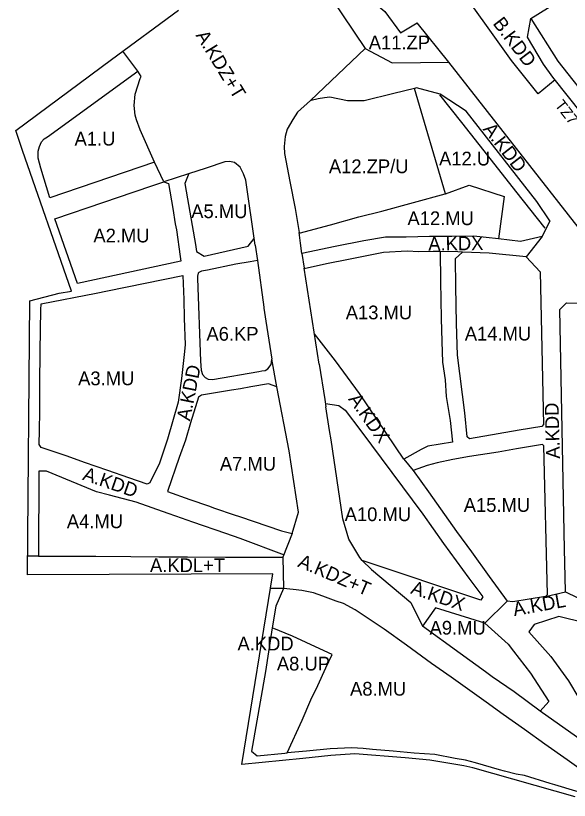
# Model space of a CAD drawing. Extents: x -292612 to -290407, y 29458 to 30862.
# Drawn here: x -292612 to -292209, y 29782 to 30353 of the extents above; entities that cross this region are included whole.
import ezdxf

# ---------------------------------------------------------------- set-up
doc = ezdxf.new("R2010")
doc.units = 0
for name, color, linetype in [('linie_rozgraniczajace', 7, 'Continuous'), ('linie_zabudowy_obowiazujace', 7, 'Continuous'), ('oznaczenia_przeznaczen', 7, 'Continuous')]:
    doc.layers.add(name, color=color, linetype=linetype)

msp = doc.modelspace()

# ---------------------------------------------------------------- linework, layer by layer
at = {"layer": 'linie_rozgraniczajace'}
for p, q in [((-292390.83, 30378.76), (-292357.67, 30329.25)), ((-292542.22, 30321.16), (-292493.29, 30357.16)), ((-292523.04, 30312.71), (-292533.81, 30327.34)), ((-292357.67, 30329.25), (-292397.33, 30291.25)), ((-292611.86, 30269.51), (-292542.22, 30321.16)), ((-292178.26, 30167.91), (-292296.67, 30319.14)), ((-292299.21, 30223.36), (-292321.61, 30300.14)), ((-292606.96, 30254.87), (-292611.86, 30269.51)), ((-292571.33, 30152.6), (-292606.96, 30254.87)), ((-292437.58, 30186.09), (-292435.97, 30174.79)), ((-292403.64, 30180.1), (-292401.98, 30169.39)), ((-292580.18, 30151.09), (-292571.33, 30152.6)), ((-292601.58, 30145.42), (-292580.18, 30151.09)), ((-292603.2, 29946.19), (-292601.58, 30145.42)), ((-292421.92, 30082.83), (-292425.54, 30102.98)), ((-292329.32, 30030.37), (-292322.65, 30022.04)), ((-292410.78, 29976.21), (-292417.39, 29959.06)), ((-292595.34, 29959.68), (-292603.09, 29959.74)), ((-292459.15, 29959.06), (-292417.39, 29959.06)), ((-292424.73, 29946.92), (-292603.2, 29946.19)), ((-292447.34, 29808.03), (-292424.73, 29946.92)), ((-292226.31, 29930.42), (-292211.9, 29933.7)), ((-292270.59, 29910.82), (-292254.33, 29927.03)), ((-292171.12, 29805.01), (-292230.27, 29846.8)), ((-292365.11, 29815.79), (-292382.58, 29814.73)), ((-292328.51, 29812.84), (-292365.11, 29815.79)), ((-292403, 29812.31), (-292447.34, 29808.03)), ((-292382.58, 29814.73), (-292403, 29812.31)), ((-292310.52, 29811.17), (-292328.51, 29812.84)), ((-292285.82, 29807.07), (-292310.52, 29811.17)), ((-292279.28, 29805.58), (-292285.82, 29807.07)), ((-292204.65, 29784.63), (-292279.28, 29805.58))]:
    msp.add_line(p, q, dxfattribs=at)
for points in [[(-292219.42, 30306.28), (-292231.76, 30296.25), (-292251.12, 30320.42), (-292294.16, 30381.19), (-292326.04, 30429.67), (-292332, 30438.9)], [(-292373.59, 30428.73), (-292377.61, 30422.97), (-292389.1, 30408.68), (-292386.8, 30405.09), (-292384.81, 30401.99), (-292384.04, 30400.78), (-292372.52, 30382.87), (-292369.66, 30378.43), (-292362.11, 30372.05), (-292343.34, 30356.18), (-292343.15, 30356.02), (-292331.87, 30340.69), (-292319.82, 30347.9)], [(-292104.75, 30221.08), (-292119.95, 30209.73), (-292121.9, 30208.54), (-292128.67, 30207.44), (-292137.35, 30208.56), (-292139.58, 30209.07), (-292145.2, 30212.99), (-292221.03, 30308.3), (-292227.7, 30317.87), (-292239.51, 30337.34), (-292236.95, 30350.95), (-292118.95, 30424.55), (-292105.07, 30421.42), (-292048.46, 30333.06)], [(-292296.67, 30319.14), (-292319.84, 30347.78)], [(-292357.67, 30329.25), (-292337.84, 30318.78), (-292296.67, 30319.14)], [(-292510.88, 30246.53), (-292586.98, 30220.6), (-292593.61, 30242.05), (-292595.6, 30249.37), (-292595.46, 30254.49), (-292594.55, 30257.84), (-292593.07, 30261.14), (-292591.05, 30263.39), (-292588.72, 30265.01), (-292523.04, 30312.71)], [(-292510.88, 30246.53), (-292521.31, 30269.91), (-292523.96, 30277.35), (-292524.82, 30280.64), (-292525.6, 30287.72), (-292525.04, 30295.91), (-292521.2, 30307.37), (-292520.59, 30308.76), (-292523.04, 30312.71)], [(-292321.61, 30300.14), (-292336.68, 30296.44), (-292358.39, 30291.14), (-292370.54, 30291.21), (-292383.33, 30293.83), (-292387.1, 30293.18), (-292391.72, 30292.58), (-292396.92, 30291.46), (-292397.33, 30291.26)], [(-292223.31, 30203.67), (-292232.56, 30217.79), (-292284.14, 30283.67), (-292303.11, 30295.89), (-292320.16, 30300.49), (-292321.61, 30300.14)], [(-292397.33, 30291.26), (-292406.71, 30282.73), (-292410.29, 30277.51), (-292414.35, 30270.36), (-292415.9, 30265.22), (-292416.41, 30257.98), (-292416.28, 30252.75), (-292412.45, 30232.41), (-292408.61, 30212.68), (-292405.65, 30195.25)], [(-292503.99, 30232.22), (-292510.88, 30246.53)], [(-292437.58, 30186.09), (-292444.36, 30233.36), (-292446, 30238.08), (-292448.6, 30242.87), (-292452.61, 30246.1), (-292456.33, 30247.03), (-292459.78, 30246.62), (-292473.34, 30242.16), (-292486.19, 30237.93)], [(-292485.8, 30238.24), (-292488.68, 30230.98), (-292486.79, 30219.73), (-292481.07, 30186.55), (-292480.24, 30181.44), (-292474.74, 30178.07), (-292442.66, 30185.3), (-292438.22, 30190.92)], [(-292486.19, 30237.93), (-292503.99, 30232.22)], [(-292503.99, 30232.22), (-292500.62, 30230.94), (-292497.52, 30212.79), (-292495.74, 30201.65), (-292494.89, 30197.18), (-292492.14, 30177.89), (-292491.64, 30174.43), (-292566.86, 30158.22), (-292583.32, 30205.12), (-292547.61, 30217.29), (-292526.5, 30224.54), (-292511.45, 30229.74), (-292503.99, 30232.22)], [(-292299.21, 30223.36), (-292281.9, 30229.74), (-292256.51, 30221.54), (-292260.56, 30190.72)], [(-292405.58, 30194.82), (-292382.74, 30200.76), (-292362.12, 30206.63), (-292345.4, 30210.81), (-292299.25, 30223.35), (-292299.21, 30223.36)], [(-292223.31, 30203.67), (-292228.69, 30192.33), (-292244.62, 30188.82), (-292260.56, 30190.72)], [(-292403.64, 30180.1), (-292404.51, 30187.52), (-292405.65, 30195.25)], [(-292260.56, 30190.72), (-292278.56, 30192.53), (-292294.6, 30192.41), (-292310.67, 30192.25), (-292327.65, 30191.77), (-292342.82, 30191.77), (-292358.53, 30189.23), (-292379.34, 30185.11), (-292403.64, 30180.08)], [(-292228.69, 30192.33), (-292240.43, 30177.61)], [(-292303.08, 30181.45), (-292308.08, 30181.4), (-292318.55, 30181.29), (-292326.96, 30181.61), (-292344.12, 30180.75), (-292369.68, 30175.6), (-292385.66, 30172.53), (-292401.9, 30168.87)], [(-292303.08, 30181.45), (-292302.75, 30159.84), (-292302.22, 30132.7), (-292301.78, 30115.91), (-292301.25, 30100.92), (-292299.26, 30088.08), (-292298.52, 30076.01), (-292295.82, 30058.55), (-292293.96, 30042.74), (-292312.03, 30039.67), (-292316.8, 30037.42), (-292329.32, 30030.37)], [(-292286.85, 30181.03), (-292290.21, 30181.18), (-292303.08, 30181.45)], [(-292230.24, 30166.67), (-292227.69, 30055.5), (-292229, 30053.98), (-292245.6, 30051.34), (-292260.85, 30048.83), (-292281.55, 30045.14), (-292283.36, 30046.64), (-292285.03, 30063.92), (-292290.44, 30106.05), (-292291.04, 30128.92), (-292291.65, 30155.89), (-292291.8, 30176.25), (-292286.85, 30181.03)], [(-292230.24, 30166.67), (-292240.43, 30177.61), (-292267.29, 30180.17), (-292286.85, 30181.03)], [(-292435.97, 30174.79), (-292441.23, 30173.96), (-292451.65, 30172.22), (-292472.3, 30167.9), (-292476.6, 30167.15), (-292478.52, 30166.21), (-292479.06, 30165.64), (-292479.63, 30163.6), (-292479.51, 30161.85), (-292477.35, 30101.67), (-292476.81, 30094.96), (-292475.87, 30091.9), (-292473.96, 30089.72), (-292471.78, 30088.63), (-292468.7, 30088.17), (-292434.99, 30094.13), (-292432.72, 30094.49), (-292430.36, 30094.87), (-292428.34, 30096.04), (-292426.06, 30099.3), (-292425.54, 30102.98)], [(-292435.97, 30174.79), (-292431.27, 30140.98), (-292431.19, 30140.31), (-292429.79, 30130.75), (-292425.54, 30102.98)], [(-292529.55, 30016.66), (-292544.84, 30022.07), (-292561.85, 30027.93), (-292574.47, 30032.38), (-292593.37, 30038.77), (-292594.68, 30040.87), (-292594.58, 30051.33), (-292594.34, 30065.05), (-292594.25, 30084.73), (-292593.97, 30109.14), (-292593.62, 30138.97), (-292593.28, 30143.23), (-292553.42, 30151.17), (-292545.11, 30152.86), (-292490.19, 30163.98), (-292489.63, 30146.39), (-292489.18, 30132.93), (-292488.54, 30113.62), (-292489.26, 30106.43), (-292491.21, 30088.89), (-292493.56, 30071.81), (-292501.43, 30044.81), (-292507.14, 30027.27), (-292514.17, 30013.07), (-292516.09, 30012.11), (-292529.55, 30016.66)], [(-292391.15, 30099.43), (-292401.98, 30169.39)], [(-292211.9, 29933.7), (-292212.1, 29944.67), (-292212.64, 29964.75), (-292215.94, 30139.28), (-292211.03, 30144.17), (-292200.78, 30143.94), (-292186.77, 30104.64), (-292127.96, 30045.4), (-292126.81, 30035.44), (-292165.71, 29962.95), (-292180.32, 29923.57), (-292186.33, 29921.37)], [(-292329.32, 30030.37), (-292361.8, 30078.01), (-292379.21, 30101.87), (-292394.55, 30121.41)], [(-292391.16, 30099.51), (-292387, 30073.67), (-292386.16, 30068.33)], [(-292421.92, 30082.83), (-292427.86, 30085.08), (-292440.65, 30082.83), (-292448.33, 30081.47), (-292454.95, 30080.43), (-292476.55, 30076.78), (-292478.88, 30075.3), (-292484.6, 30056.7), (-292488.3, 30044.2), (-292493, 30031.58), (-292501.4, 30006.67), (-292485.05, 30000.9), (-292471.46, 29996.24), (-292467.2, 29994.56), (-292452.87, 29989.7), (-292449.01, 29988.64), (-292418.54, 29978.12), (-292410.78, 29976.21)], [(-292410.78, 29976.21), (-292406.06, 29991.75), (-292412.89, 30036.24), (-292421.92, 30082.83)], [(-292386.55, 30070.77), (-292376.77, 30069.27), (-292372.17, 30066.05), (-292360.8, 30050.87), (-292315.61, 29990.37), (-292300.61, 29969.01), (-292282.21, 29943.8), (-292272.01, 29930.03), (-292273.49, 29927.62), (-292359.76, 29956.59)], [(-292359.76, 29956.59), (-292361.55, 29958.76), (-292369.47, 29972.04), (-292373.73, 29986.9), (-292382.4, 30044.25), (-292383.53, 30051.08), (-292386.16, 30068.33)], [(-292226.31, 29930.42), (-292224.79, 29931.84), (-292227.5, 30040), (-292228.62, 30041.05), (-292247.4, 30037.78), (-292260.9, 30035.5), (-292281.59, 30032.22), (-292293.83, 30030.16), (-292305.13, 30027.64), (-292312.54, 30025.79), (-292322.65, 30022.04)], [(-292416.34, 29960.48), (-292448.46, 29972.47), (-292458.99, 29976.14), (-292483.07, 29984.54), (-292495.37, 29988.81), (-292500.93, 29990.7), (-292524.32, 29998.88), (-292543.52, 30004.15), (-292553.13, 30006.53), (-292589.35, 30021.46), (-292594.99, 30021.46), (-292595.34, 29959.68)], [(-292322.65, 30022.04), (-292311.42, 30006.44), (-292291, 29977.75), (-292280.08, 29962.84), (-292267.22, 29944.81), (-292254.33, 29927.03)], [(-292595.34, 29959.68), (-292553.66, 29959.64), (-292528.1, 29959.38), (-292507.8, 29959.28), (-292486.73, 29959.25), (-292459.15, 29959.06)], [(-292417.39, 29959.06), (-292417.09, 29936.06)], [(-292359.76, 29956.59), (-292352.92, 29949.87), (-292324.27, 29925.87), (-292315.91, 29908.72)], [(-292417.09, 29936.06), (-292426.49, 29936.07)], [(-292417.09, 29936.06), (-292422.53, 29923.22), (-292425.23, 29907.56)], [(-292176.13, 29786.65), (-292196.11, 29800.91), (-292210.7, 29811.42), (-292226.79, 29822.79), (-292241.71, 29833.57), (-292257.21, 29844.57), (-292269.58, 29853.38), (-292281.3, 29861.8), (-292295.02, 29871.61), (-292309.25, 29881.48), (-292327.43, 29894.85), (-292343.8, 29906.62), (-292364.93, 29920.68), (-292373.24, 29925.15), (-292378.63, 29927), (-292388.33, 29930.59), (-292395.2, 29933), (-292403.59, 29934.7), (-292409.88, 29935.52), (-292417.09, 29936.06)], [(-292226.31, 29930.42), (-292250.2, 29926.4), (-292254.33, 29927.03)], [(-292211.9, 29933.7), (-292194.24, 29925.25), (-292186.33, 29921.37)], [(-292270.59, 29910.82), (-292306.49, 29922.1), (-292315.91, 29908.72)], [(-291997.89, 29864.27), (-292011.86, 29863.38), (-292018.37, 29863.29), (-292040.84, 29865.39), (-292047.97, 29865.95), (-292072.31, 29869.28), (-292095.86, 29873.28), (-292122.04, 29877.72), (-292138.55, 29880.13), (-292175.49, 29898.85), (-292194.21, 29908.17), (-292198.39, 29909.92), (-292198.03, 29911.14), (-292216.69, 29915.79), (-292234.71, 29910.07), (-292238.43, 29904.69), (-292222.57, 29886.61), (-292209.52, 29868.85), (-292202.01, 29856.35), (-292193.02, 29835.97), (-292186.08, 29825.88), (-292171.12, 29805.01)], [(-292425.23, 29907.56), (-292430.18, 29875.78), (-292440.29, 29817.84), (-292436.04, 29814.27), (-292416.03, 29816.36), (-292414.25, 29816.53)], [(-292414.25, 29816.53), (-292403.33, 29840.34), (-292397.09, 29855.13), (-292392.03, 29865.56), (-292386.15, 29878.54), (-292381.49, 29888.16), (-292390.44, 29892.23), (-292410.56, 29901.38), (-292425.23, 29907.56)], [(-292414.25, 29816.53), (-292403.33, 29840.34), (-292397.09, 29855.13), (-292392.03, 29865.56), (-292386.15, 29878.54), (-292381.49, 29888.16), (-292390.44, 29892.23), (-292410.56, 29901.38), (-292425.23, 29907.56)], [(-292230.27, 29846.8), (-292249.12, 29861), (-292265.08, 29871.98), (-292269.9, 29875.49), (-292288.47, 29888.82), (-292315.91, 29908.72)], [(-292270.59, 29910.82), (-292253.51, 29895.66), (-292249.63, 29890.53), (-292237.2, 29874.65), (-292223.9, 29853.84), (-292230.27, 29846.8)], [(-292176.13, 29786.65), (-292179.9, 29782), (-292195.99, 29786.46), (-292204.16, 29788.73), (-292219.53, 29793.15), (-292222.85, 29794.21), (-292241.54, 29800.15), (-292247.59, 29801.03), (-292256.25, 29803.2), (-292259.91, 29804.26), (-292277.27, 29809.28), (-292284.64, 29811.13), (-292292.09, 29812.37), (-292306.82, 29815.42), (-292322.02, 29816.42), (-292337.28, 29817.73), (-292352.2, 29818.98), (-292358.98, 29819.79), (-292367.32, 29820.24), (-292383.03, 29819.54), (-292400.19, 29817.82), (-292414.25, 29816.53)]]:
    msp.add_lwpolyline(points, dxfattribs=at)
at = {"layer": 'linie_zabudowy_obowiazujace'}
for points in [[(-292236.94, 30350.95), (-292217.25, 30319.88), (-292190.86, 30286.45), (-292188.03, 30278.34), (-292150.43, 30230.39), (-292133.52, 30208.07)], [(-292226.63, 30198.31), (-292247.96, 30225.3), (-292268.37, 30251.37), (-292287.14, 30275.33), (-292303.19, 30295.58)]]:
    msp.add_lwpolyline(points, dxfattribs=at)

# ---------------------------------------------------------------- texts
at = {"layer": 'oznaczenia_przeznaczen'}
for s, height, rotation, p in [('B.KDD', 10, 307.3299, (-292265.09, 30347.32)), ('A.KDZ+T', 10, 301.3309, (-292481.2, 30338.78)), ('TZ7', 8, 307.875, (-292219.92, 30287.92)), ('A.KDD', 10, 308.0558, (-292272.29, 30270.32)), ('A.KDX', 10, 0.5762, (-292311.59, 30182.08)), ('A.KDD', 10, 78.8028, (-292485.06, 30057.7)), ('A.KDX', 10, 305.0793, (-292370.16, 30073.94)), ('A.KDD', 10, 91.4688, (-292215.85, 30030.71)), ('A.KDD', 10, 340.9978, (-292563.82, 30015.47)), ('A.KDZ+T', 10, 336.8515, (-292407.22, 29952.31)), ('A.KDX', 10, 340.9978, (-292325.04, 29932.7)), ('A.KDL', 10, 10.2641, (-292249.07, 29916))]:
    msp.add_text(s, height=height, rotation=rotation, dxfattribs=at).set_placement(p)
for s, p in [('A11.ZP', (-292354.96, 30328.58)), ('A1.U', (-292569.04, 30258.54)), ('A12.U', (-292303.79, 30244.06)), ('A12.ZP/U', (-292383.96, 30238.43)), ('A5.MU', (-292484.14, 30205.71)), ('A12.MU', (-292326.78, 30200.62)), ('A2.MU', (-292555.32, 30188.03)), ('A13.MU', (-292371.7, 30132.08)), ('A6.KP', (-292473.07, 30116.51)), ('A14.MU', (-292285.07, 30116.66)), ('A3.MU', (-292566.42, 30084.1)), ('A7.MU', (-292463.29, 30021.95)), ('A15.MU', (-292285.84, 29991.93)), ('A10.MU', (-292372.48, 29985.19)), ('A4.MU', (-292574.66, 29980.04)), ('A.KDL+T', (-292514.14, 29948.13)), ('A9.MU', (-292310.71, 29902.6)), ('A.KDD', (-292450.47, 29891.06)), ('A8.UP', (-292421.82, 29876.48)), ('A8.MU', (-292368.56, 29858.17))]:
    msp.add_text(s, height=10, dxfattribs=at).set_placement(p)

doc.saveas('drawing.dxf')
